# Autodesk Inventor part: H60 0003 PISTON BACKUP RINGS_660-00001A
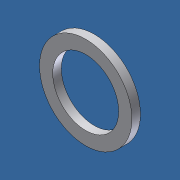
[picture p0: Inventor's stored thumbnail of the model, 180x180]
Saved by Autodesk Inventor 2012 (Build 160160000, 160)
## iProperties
Created: 2013-10
Part Number: H60 0003 PISTON BACKUP RINGS_660-00001A
Material: Default
Document SubType Name: Modeling
Designer: Admin
Density: 1 g/cm^3
Author: Admin
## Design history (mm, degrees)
node "H60 0003 PISTON BACKUP RINGS_660-00001A1"
node "Base1"
body "Solid1"
